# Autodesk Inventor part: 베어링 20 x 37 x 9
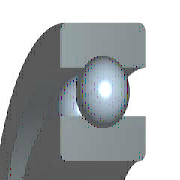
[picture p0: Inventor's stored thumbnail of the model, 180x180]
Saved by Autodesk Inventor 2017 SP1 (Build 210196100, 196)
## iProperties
IsCustomPart: 1
Created: 2012-02
Part Number: 베어링 20 x 37 x 9
Material: 강철, 연강
Description: 깊은 그루브 볼 베어링
Document SubType Name: Modeling
Standard: KS B 2023
Designer: mduedu
Standards Organization: KS
Language: ko-KR
Size Designation: 6904 - 20 x 37 x 9
Categories: <MemberInstance><Categories><Category DisplayName="샤프트 부품" InternalName="7f7aeb1f-a693-4053-b835-cee3144e0d98" Mnemonic="SHFT"><Category DisplayName="베어링" Inter
Density: 7.86 g/cm^3
Mass: 36.2613 g
Surface Area: 48.5817 cm^2
Volume: 4.61339 cm^3
Appearance: 노란색
Author: mduedu
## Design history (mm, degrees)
sketch "스케치" dims "d0" = 4.42 (= -0.26 x WD + 0.26 x BD)
  geometry: L1 (2.29, 14.25)-(6.71, 14.25); L2 (4.5, 14.25)-(4.5, 12.04); L3 (4.5, 14.25)-(4.5, 16.46); L4 (2.858, 12.771)-(0, 12.771); L5 (0, 10)-(9, 10); L6 (2.858, 15.729)-(0, 15.729); L7 (0, 18.5)-(9, 18.5); L8 (9, 10)-(9, 12.771); L9 (6.142, 12.771)-(9, 12.771); L10 (6.142, 15.729)-(9, 15.729); L11 (9, 18.5)-(9, 15.729); L12 (-1.4, 0)-(8.4, 0) reference; L13 (0, -0.3)-(0, 5.3) reference
  constraints: 22 end point, 4 point on line, 2 collinear, 2 perpendicular, 2 symmetric about line, 1 midpoint, 1 parallel, 14 other
  dimensions: "d9" = 20 diameter of L5 L12 (= WD); "d11" = 37 diameter of L7 L12 (= BD); "d12" = 9 distance between parallel lines of L8 L13 (= KB); "d13" = 25.542 diameter of L9 L12 (= 0.326 x BD + 0.674 x WD)
revolve "본체" stored, may be unused: angle "d6" = 90 deg
revolve "볼" stored, may be unused: angle "d7" = 90 deg
pattern_circular "IDS_ARRAYBALL[SIMPL:T]" dims angle "d3" = 360 deg
body "Solid1"
fillet "모깎기1" dims "d1" = 0.3 (= KRS)
other parameters: "WD" = 20 [user parameter; used in 5 equation terms], "BD" = 37 [user parameter; used in 5 equation terms], "KB" = 9 [user parameter; used in 1 equation term], "KRS" = 0.3 [user parameter; used in 1 equation term], "d4" = 0, "d5" = 0, "d8" = 0, "d14" = 0, "d15" = 0, "BBA" = 0 [user parameter], "BC0" = 3304000 [user parameter], "BC" = 6184000 [user parameter], "BR" = 18.5 (= 0.5 x BD) [user parameter]
